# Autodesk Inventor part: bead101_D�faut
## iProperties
Created: 2011-01
Part Number: bead101_D�faut
Document SubType Name: Modeling
Designer: eric
Density: 1 g/cm^3
Mass: 0.0356546 g
Surface Area: 1.11254 cm^2
Volume: 0.0356546 cm^3
Author: eric
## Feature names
1. Base1
